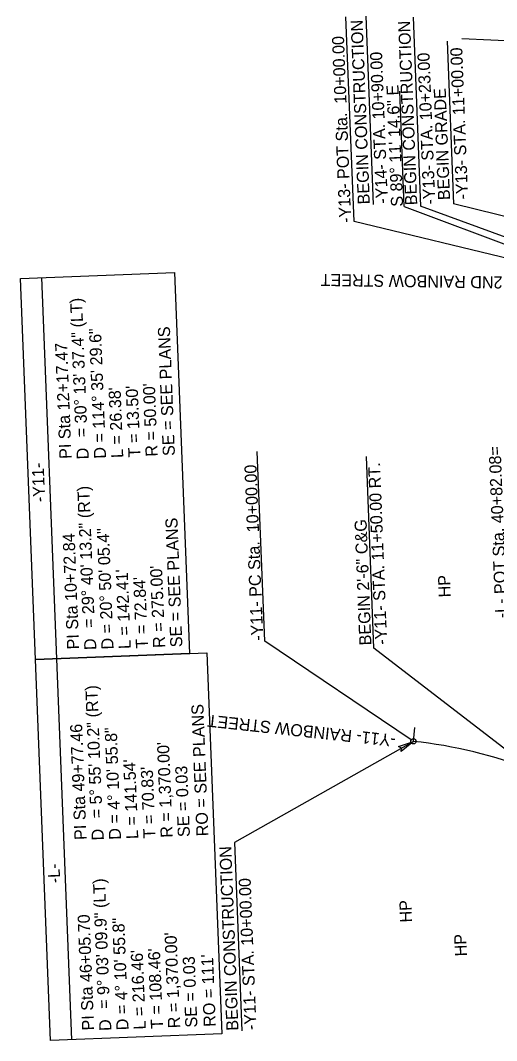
# Model space of a CAD drawing. Extents: x 1627861 to 1629601, y 761281 to 766239.
# Drawn here: x 1627883 to 1628160, y 764223 to 764815 of the extents above; entities that cross this region are included whole.
import ezdxf

# ---------------------------------------------------------------- set-up
doc = ezdxf.new("R2010")
doc.units = 0
for name, color, linetype in [('Cogo Default Point CELL', 7, 'Continuous'), ('Exist Hydro Jurisdictional Stream or Body of Water', 7, 'Continuous'), ('Exist Other Culture Sign Leader', 7, 'Continuous'), ('Exist Right of Way Line Leader', 7, 'Continuous'), ('Exist Utilities Gas Meter CELL', 7, 'Continuous'), ('Exist Utilities Gas Meter Cogo Number', 7, 'Continuous'), ('Exist Utilities Gas UG Line Text', 7, 'Continuous'), ('Exist Utilities Power UG Cable SUE LOS B Cogo Point CELL', 7, 'Continuous'), ('Exist Utilities Water Fire Hydrant Cogo Number', 7, 'Continuous'), ('Exist Utilities Water Meter Cogo Elevation', 7, 'Continuous'), ('Scratch_Level_0', 7, 'Continuous')]:
    doc.layers.add(name, color=color, linetype=linetype)

msp = doc.modelspace()

# ---------------------------------------------------------------- linework, layer by layer
at = {"layer": 'Exist Hydro Jurisdictional Stream or Body of Water'}
msp.add_arc((1628081.99, 764123.59), 275, 54.17473, 83.84505, dxfattribs=at)
at = {"layer": 'Exist Right of Way Line Leader'}
for p, q in [((1628077.02, 764698.58), (1628072.33, 764817.34)), ((1628106.19, 764707.24), (1628103.55, 764774.24)), ((1628106.19, 764707.24), (1628206.07, 764669.75)), ((1628196.39, 764669.89), (1628077.02, 764698.58)), ((1628025.21, 764455.21), (1628020.87, 764565.2)), ((1628110.24, 764397.85), (1628025.21, 764455.21))]:
    msp.add_line(p, q, dxfattribs=at)
msp.add_circle((1628111.48, 764397.01), 1.5, dxfattribs=at)
at = {"layer": 'Exist Utilities Gas Meter CELL'}
msp.add_arc((1628081.99, 764123.59), 275, 54.17473, 83.84505, dxfattribs=at)
at = {"layer": 'Exist Utilities Gas Meter Cogo Number'}
msp.add_lwpolyline([(1628102.88, 764393.93), (1628111.48, 764397.01), (1628104.39, 764391.16), (1628104.6, 764393.12)], close=True, dxfattribs=at)
at = {"layer": 'Exist Utilities Gas UG Line Text'}
for p, q in [((1627895.66, 764666.04), (1627904.38, 764444.96)), ((1627904.38, 764444.96), (1627913.09, 764223.89))]:
    msp.add_line(p, q, dxfattribs=at)
for points in [[(1627892.04, 764444.48), (1627883.32, 764665.55), (1627972.86, 764669.08), (1627981.58, 764448.01)], [(1627900.76, 764223.4), (1627892.04, 764444.48), (1627991.5, 764448.4), (1628000.22, 764227.32)]]:
    msp.add_lwpolyline(points, close=True, dxfattribs=at)
at = {"layer": 'Exist Utilities Water Fire Hydrant Cogo Number'}
msp.add_line((1628314.21, 764796.74), (1628139.67, 764804.6), dxfattribs=at)
at = {"layer": 'Exist Utilities Water Meter Cogo Elevation'}
msp.add_line((1628111.48, 764397.01), (1628112.34, 764404.96), dxfattribs=at)
at = {"layer": 'Scratch_Level_0'}
for p, q in [((1628083.84, 764817.64), (1628088.14, 764708.47)), ((1628111.37, 764817.14), (1628115.69, 764707.44)), ((1628131.08, 764803.24), (1628134.8, 764708.93)), ((1628219.39, 764669.56), (1628115.69, 764707.44)), ((1628296.38, 764668.47), (1628134.8, 764708.93)), ((1628088.56, 764451.03), (1628084.17, 764562.34)), ((1628242.39, 764332.8), (1628088.56, 764451.03)), ((1628111.48, 764397.01), (1628007.57, 764338.25)), ((1628007.57, 764338.25), (1628011.87, 764229.08))]:
    msp.add_line(p, q, dxfattribs=at)

# ---------------------------------------------------------------- texts
at = {"layer": 'Cogo Default Point CELL'}
msp.add_text('S 89%%d 11\' 14.6" E', height=7, rotation=92.25819, dxfattribs=at).set_placement((1628105.57, 764707.33))
at = {"layer": 'Exist Other Culture Sign Leader'}
for s, rotation, p in [('BEGIN CONSTRUCTION', 92.25819, (1628086.23, 764708.67)), ('BEGIN CONSTRUCTION', 92.25819, (1628113.76, 764708.16)), ('-Y13- STA. 11+00.00', 92.25819, (1628143.3, 764711.56)), ('-Y14- STA. 10+90.00', 92.25819, (1628096.72, 764709.08)), ('-Y13- STA. 10+23.00', 92.25819, (1628124.25, 764708.57)), ('BEGIN GRADE', 92.25819, (1628132.81, 764711.14)), ('-Y13- 2ND RAINBOW STREET', 179.18738, (1628188.77, 764666.35)), ('HP', 92.25819, (1628133.23, 764480.66)), ('-Y11- RAINBOW STREET', 173.84505, (1628101.49, 764400.75)), ('BEGIN CONSTRUCTION', 92.25819, (1628009.96, 764229.28)), ('-Y11- STA. 10+00.00', 92.25819, (1628020.45, 764229.69)), ('HP', 92.25819, (1628110.79, 764292.05)), ('HP', 92.25819, (1628142.62, 764272.39))]:
    msp.add_text(s, height=7, rotation=rotation, dxfattribs=at).set_placement(p)
at = {"layer": 'Exist Right of Way Line Leader'}
for s, p in [('-Y13- POT Sta.  10+00.00', (1628075.44, 764697.93)), ('-L- POT Sta. 40+82.08=', (1628166.06, 764468.57)), ('-Y11- PC Sta.  10+00.00', (1628024.37, 764455.51))]:
    msp.add_text(s, height=7, rotation=92.25819, dxfattribs=at).set_placement(p)
at = {"layer": 'Exist Utilities Gas UG Line Text'}
for s, rotation, p in [('= 30%%d 13\' 37.4" (LT)', 92.25819, (1627922.29, 764573.57)), ('D = 114%%d 35\' 29.6"', 92.25819, (1627933.09, 764561.14)), ('SE = SEE PLANS', 92.25804, (1627973.05, 764562.71)), ('PI Sta 12+17.47', 92.25819, (1627913.07, 764561.02)), ("R = 50.00'", 92.25819, (1627963.06, 764562.32)), ("L = 26.38'", 92.25819, (1627943.08, 764561.53)), ("T = 13.50'", 92.25819, (1627953.07, 764561.93)), ('D', 92.25819, (1627923.09, 764560.74)), ('-Y11-', 92.25819, (1627897.75, 764535.9)), ('= 29%%d 40\' 13.2" (RT)', 92.25819, (1627926.56, 764462.91)), ('SE = SEE PLANS', 92.25804, (1627977.42, 764451.74)), ('D = 20%%d 50\' 05.4"', 92.25819, (1627937.45, 764450.43)), ('PI Sta 10+72.84', 92.25819, (1627917.43, 764450.49)), ("R = 275.00'", 92.25819, (1627967.43, 764451.34)), ("L = 142.41'", 92.25819, (1627947.44, 764450.73)), ("T = 72.84'", 92.25819, (1627957.44, 764451.04)), ('D', 92.25819, (1627927.45, 764450.12)), ('= 5%%d 55\' 10.2" (RT)', 92.25497, (1627931.01, 764352.49)), ('RO = SEE PLANS', 92.25804, (1627992.54, 764342.06)), ('PI Sta 49+77.46', 92.25497, (1627921.79, 764339.94)), ('D = 4%%d 10\' 55.8"', 92.25497, (1627941.8, 764340.06)), ("R = 1,370.00'", 92.25497, (1627971.78, 764341.24)), ("L = 141.54'", 92.25497, (1627951.8, 764340.45)), ("T = 70.83'", 92.25497, (1627961.79, 764340.84)), ('SE = 0.03', 92.25804, (1627981.77, 764341.63)), ('D', 92.25497, (1627931.81, 764339.66)), ('-L-', 92.25819, (1627906.47, 764314.83)), ('= 9%%d 03\' 09.9" (LT)', 92.25804, (1627935.37, 764241.95)), ('PI Sta 46+05.70', 92.25804, (1627926.15, 764229.41)), ('D = 4%%d 10\' 55.8"', 92.25804, (1627946.16, 764229.52)), ("R = 1,370.00'", 92.25804, (1627976.14, 764230.7)), ("L = 216.46'", 92.25804, (1627956.15, 764229.91)), ("T = 108.46'", 92.25804, (1627966.15, 764230.31)), ('SE = 0.03', 92.25804, (1627986.13, 764231.1)), ("RO = 111'", 92.25804, (1627996.79, 764231.52)), ('D', 92.25804, (1627936.17, 764229.13))]:
    msp.add_text(s, height=7, rotation=rotation, dxfattribs=at).set_placement(p)
at = {"layer": 'Exist Utilities Power UG Cable SUE LOS B Cogo Point CELL'}
for s, p in [('-Y11- STA. 11+50.00 RT.', (1628096.31, 764453.17)), ('BEGIN 2\'-6" C&G', (1628087.14, 764452.81))]:
    msp.add_text(s, height=7, rotation=92.25819, dxfattribs=at).set_placement(p)

doc.saveas('drawing.dxf')
